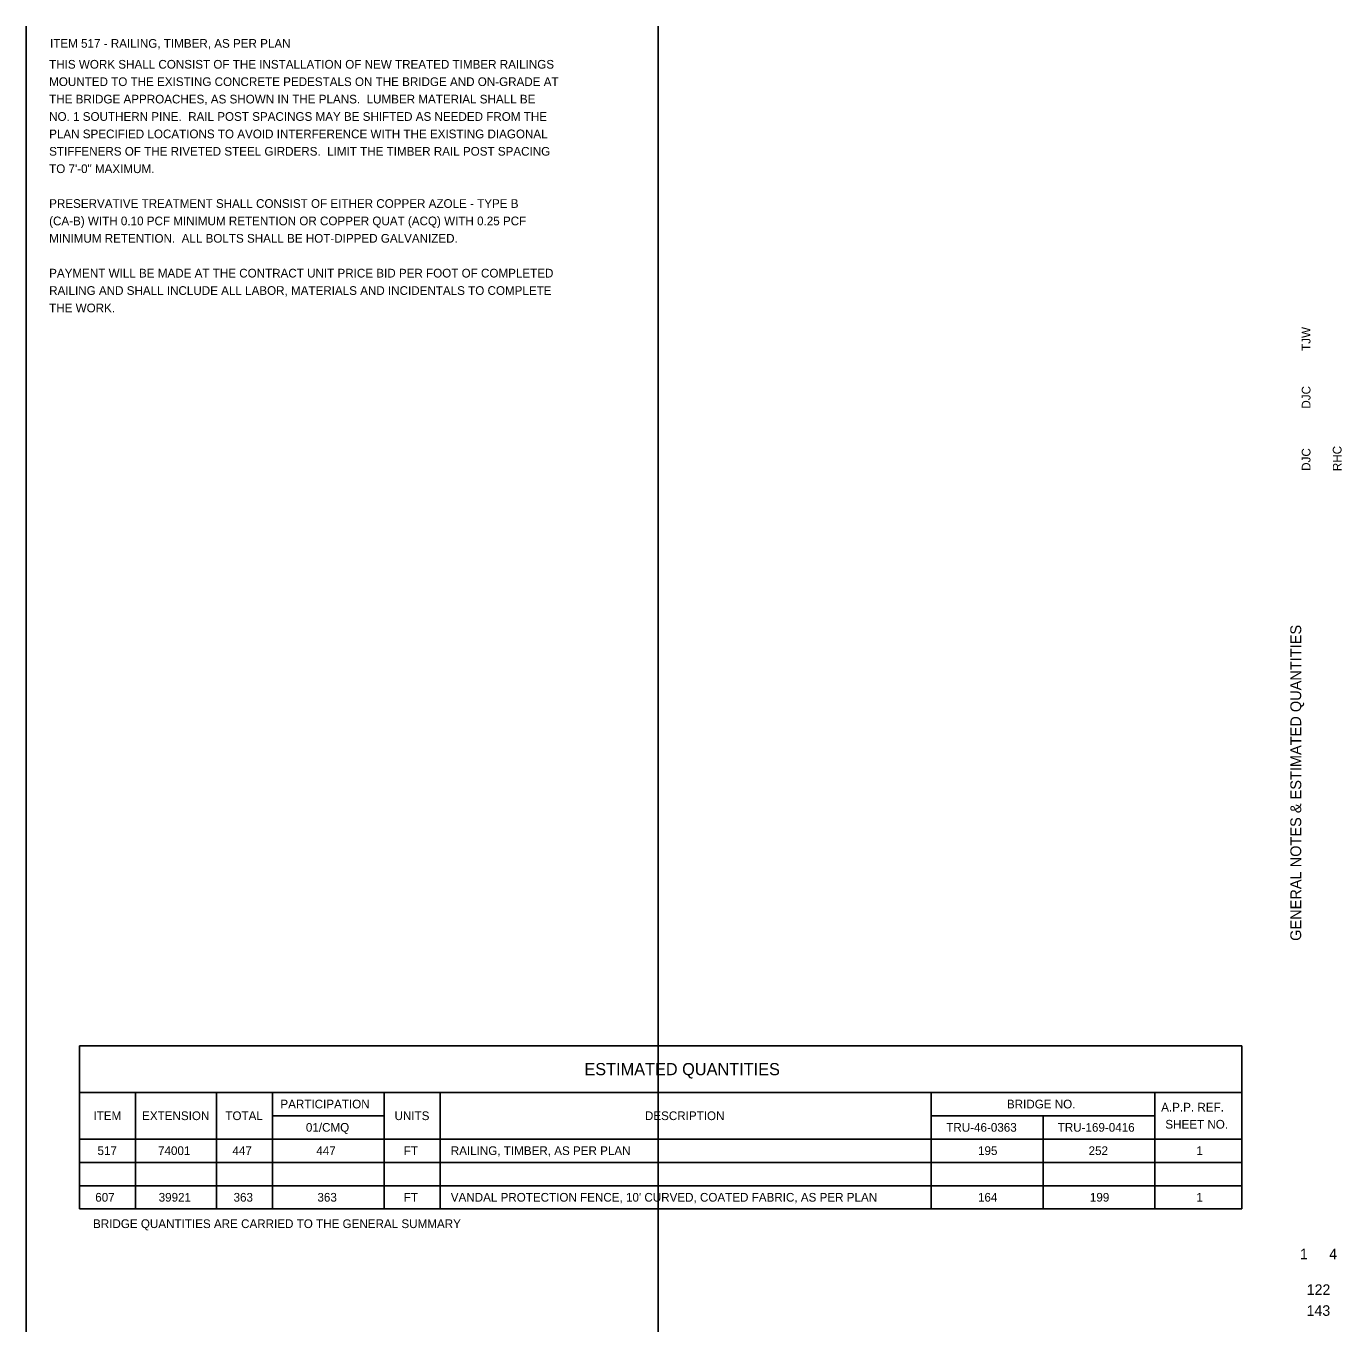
# Model space of a CAD drawing. Extents: x -10.6 to 33.4, y -28.4 to 21.5.
# Drawn here: x 12.24 to 33.41, y 0.5 to 21.5 of the extents above; entities that cross this region are included whole.
import ezdxf

# ---------------------------------------------------------------- set-up
doc = ezdxf.new("R2010")
doc.units = 0
for name, color, linetype in [('BR_P_Gen_Text', 7, 'Continuous'), ('SC_Scratch1', 7, 'Continuous'), ('SH_Data', 7, 'Continuous')]:
    doc.layers.add(name, color=color, linetype=linetype)

msp = doc.modelspace()

# ---------------------------------------------------------------- linework, layer by layer
at = {"layer": 'BR_P_Gen_Text'}
for p, q in [((13.1, 2.474), (13.1, 5.099)), ((31.8, 5.099), (13.1, 5.099)), ((31.8, 2.474), (31.8, 5.099)), ((31.8, 4.349), (13.1, 4.349)), ((14, 2.474), (14, 4.349)), ((15.3, 2.474), (15.3, 4.349)), ((16.2, 2.474), (16.2, 4.349)), ((18, 2.474), (18, 4.349)), ((18.9, 2.474), (18.9, 4.349)), ((26.8, 2.474), (26.8, 4.349)), ((30.4, 2.474), (30.4, 4.349)), ((18, 3.974), (16.2, 3.974)), ((30.4, 3.974), (26.8, 3.974)), ((28.6, 2.474), (28.6, 3.974)), ((31.8, 3.599), (13.1, 3.599)), ((31.8, 2.474), (13.1, 2.474))]:
    msp.add_line(p, q, dxfattribs=at)
at = {"layer": 'SC_Scratch1'}
for p, q in [((12.242, 0.5), (12.242, 21.5)), ((22.41, 0.5), (22.41, 21.5))]:
    msp.add_line(p, q, dxfattribs=at)
at = {"layer": 'SH_Data'}
for p, q in [((31.8, 3.224), (13.1, 3.224)), ((31.8, 2.849), (13.1, 2.849))]:
    msp.add_line(p, q, dxfattribs=at)

# ---------------------------------------------------------------- texts
at = {"layer": 'BR_P_Gen_Text'}
for s, height, p in [('ITEM 517 - RAILING, TIMBER, AS PER PLAN', 0.14, (12.623, 21.155)), ('THIS WORK SHALL CONSIST OF THE INSTALLATION OF NEW TREATED TIMBER RAILINGS', 0.14, (12.609, 20.819)), ('MOUNTED TO THE EXISTING CONCRETE PEDESTALS ON THE BRIDGE AND ON-GRADE AT', 0.14, (12.609, 20.539)), ('THE BRIDGE APPROACHES, AS SHOWN IN THE PLANS.  LUMBER MATERIAL SHALL BE', 0.14, (12.609, 20.259)), ('NO. 1 SOUTHERN PINE.  RAIL POST SPACINGS MAY BE SHIFTED AS NEEDED FROM THE', 0.14, (12.609, 19.979)), ('PLAN SPECIFIED LOCATIONS TO AVOID INTERFERENCE WITH THE EXISTING DIAGONAL', 0.14, (12.609, 19.699)), ('STIFFENERS OF THE RIVETED STEEL GIRDERS.  LIMIT THE TIMBER RAIL POST SPACING', 0.14, (12.609, 19.419)), ('TO 7\'-0" MAXIMUM.', 0.14, (12.609, 19.139)), ('PRESERVATIVE TREATMENT SHALL CONSIST OF EITHER COPPER AZOLE - TYPE B', 0.14, (12.609, 18.579)), ('(CA-B) WITH 0.10 PCF MINIMUM RETENTION OR COPPER QUAT (ACQ) WITH 0.25 PCF', 0.14, (12.609, 18.299)), ('MINIMUM RETENTION.  ALL BOLTS SHALL BE HOT-DIPPED GALVANIZED.', 0.14, (12.609, 18.019)), ('PAYMENT WILL BE MADE AT THE CONTRACT UNIT PRICE BID PER FOOT OF COMPLETED', 0.14, (12.609, 17.459)), ('RAILING AND SHALL INCLUDE ALL LABOR, MATERIALS AND INCIDENTALS TO COMPLETE', 0.14, (12.609, 17.179)), ('THE WORK.', 0.14, (12.609, 16.899)), ('ESTIMATED QUANTITIES', 0.196, (21.221, 4.626)), ('PARTICIPATION', 0.14, (16.33, 4.092)), ('BRIDGE NO.', 0.14, (28.019, 4.092)), ('ITEM', 0.14, (13.322, 3.904)), ('EXTENSION', 0.14, (14.105, 3.904)), ('TOTAL', 0.14, (15.444, 3.904)), ('UNITS', 0.14, (18.166, 3.904)), ('DESCRIPTION', 0.14, (22.195, 3.904)), ('A.P.P. REF.', 0.14, (30.501, 4.042)), ('01/CMQ', 0.14, (16.74, 3.717)), ('TRU-46-0363', 0.14, (27.043, 3.717)), ('TRU-169-0416', 0.14, (28.836, 3.717)), ('SHEET NO.', 0.14, (30.568, 3.767)), ('517', 0.14, (13.387, 3.342)), ('74001', 0.14, (14.361, 3.342)), ('447', 0.14, (15.558, 3.342)), ('447', 0.14, (16.908, 3.342)), ('FT', 0.14, (18.315, 3.342)), ('RAILING, TIMBER, AS PER PLAN', 0.14, (19.071, 3.342)), ('195', 0.14, (27.554, 3.342)), ('252', 0.14, (29.333, 3.342)), ('1', 0.14, (31.066, 3.342)), ('607', 0.14, (13.351, 2.592)), ('39921', 0.14, (14.371, 2.592)), ('363', 0.14, (15.576, 2.592)), ('363', 0.14, (16.926, 2.592)), ('FT', 0.14, (18.315, 2.592)), ("VANDAL PROTECTION FENCE, 10' CURVED, COATED FABRIC, AS PER PLAN", 0.14, (19.071, 2.592)), ('164', 0.14, (27.553, 2.592)), ('199', 0.14, (29.354, 2.592)), ('1', 0.14, (31.066, 2.592)), ('BRIDGE QUANTITIES ARE CARRIED TO THE GENERAL SUMMARY', 0.14, (13.315, 2.167))]:
    msp.add_text(s, height=height, dxfattribs=at).set_placement(p)
at = {"layer": 'SH_Data'}
for s, height, p in [('TJW', 0.14, (32.903, 16.278)), ('DJC', 0.14, (32.903, 15.349)), ('DJC', 0.14, (32.903, 14.349)), ('RHC', 0.14, (33.403, 14.344)), ('GENERAL NOTES & ESTIMATED QUANTITIES', 0.175, (32.754, 6.787))]:
    msp.add_text(s, height=height, rotation=90, dxfattribs=at).set_placement(p)
for s, p in [('1', (32.734, 1.665)), ('4', (33.204, 1.665)), ('122', (32.843, 1.091)), ('143', (32.841, 0.755))]:
    msp.add_text(s, height=0.17, dxfattribs=at).set_placement(p)

doc.saveas('drawing.dxf')
